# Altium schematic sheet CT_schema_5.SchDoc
size 573 x 363 mm
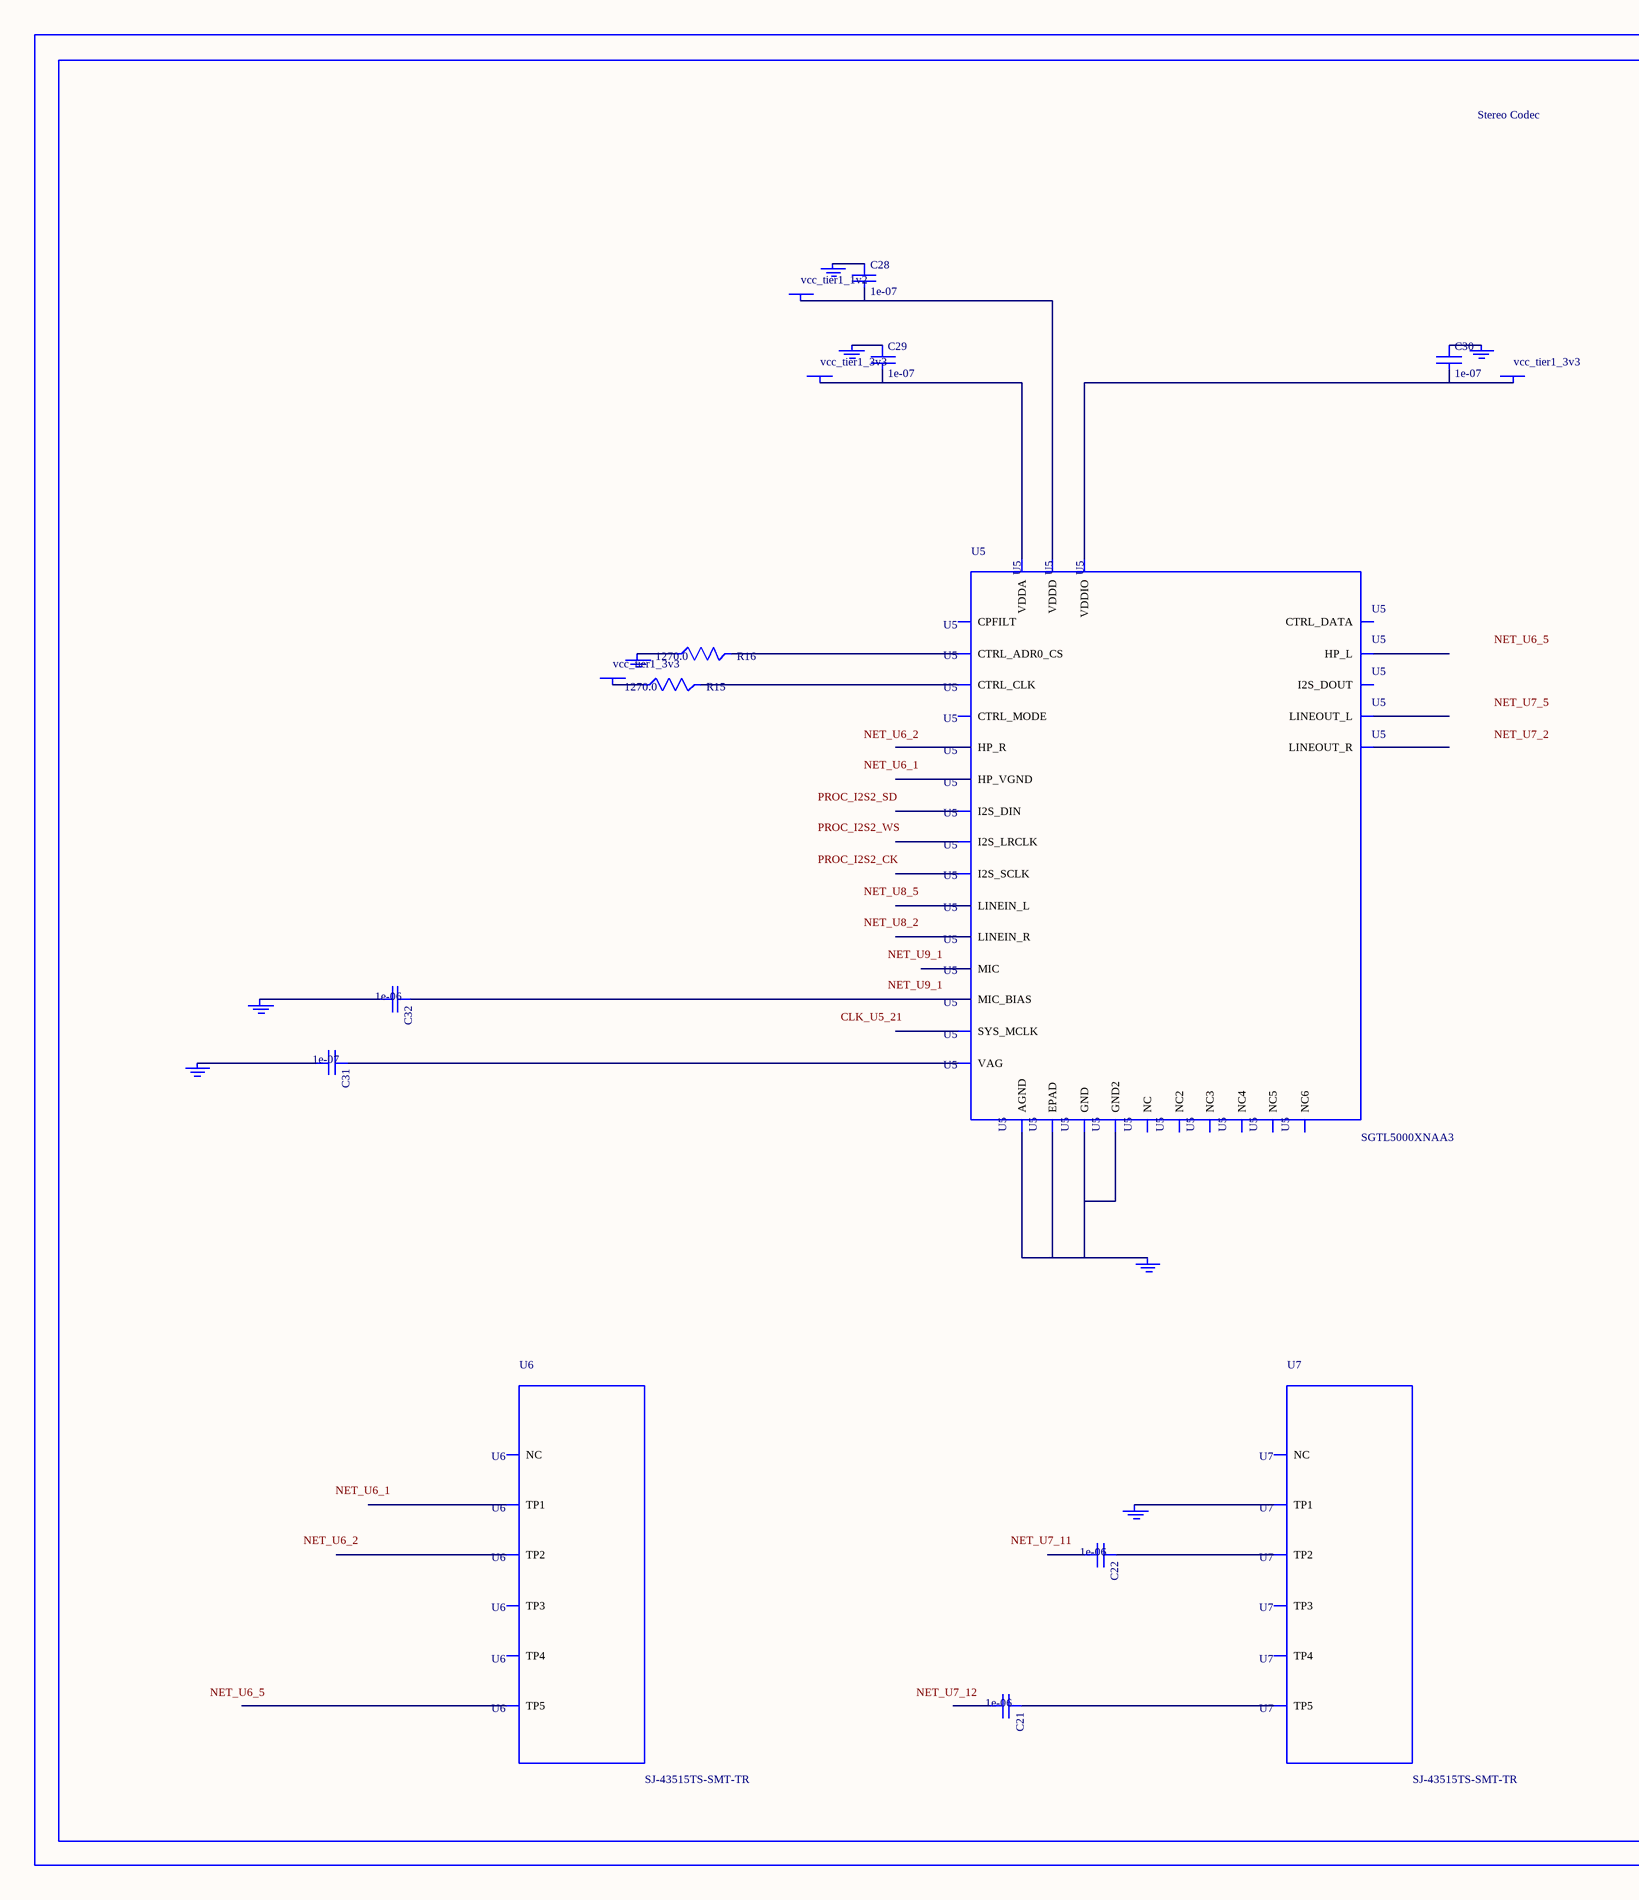
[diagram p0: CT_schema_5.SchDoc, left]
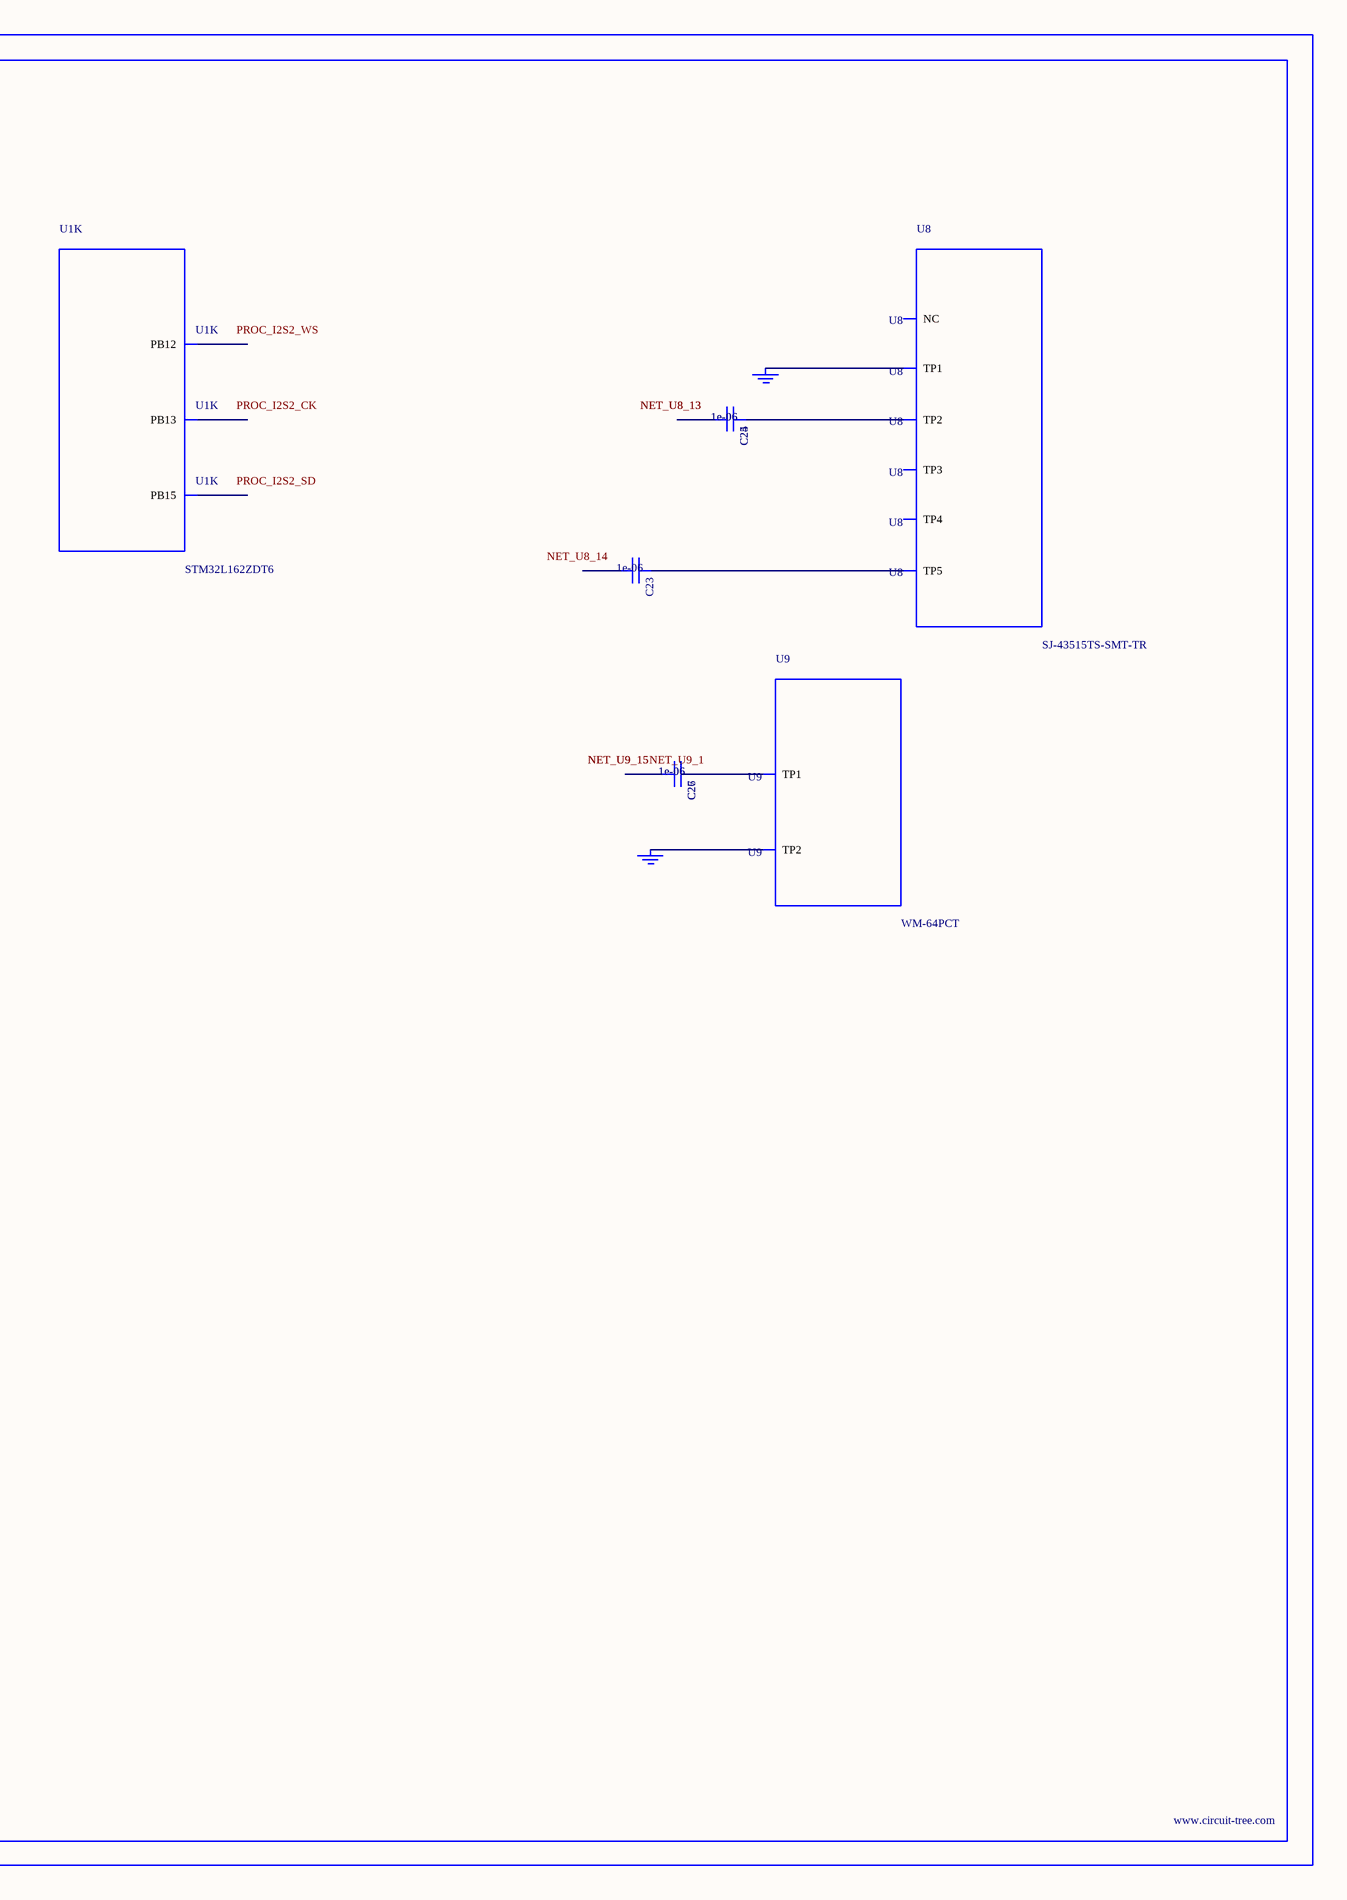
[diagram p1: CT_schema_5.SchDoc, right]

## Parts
BORDER4  (no value)
C21  1e-06  [C0603]
C22  1e-06  [C0603]
C23  1e-06  [C0603]
C24  1e-06  [C0603]
C25  1e-06  [C0603]
C26  1e-06  [C0603]
C27  1e-06  [C0603]
C28  1e-07  [C0402]
C29  1e-07  [C0402]
C30  1e-07  [C0402]
C31  1e-07  [C0402]
C32  1e-06  [C0603]
GND_INSTANCE_4_0  (no value)
GND_INSTANCE_4_1  (no value)
GND_INSTANCE_4_2  (no value)
GND_INSTANCE_4_3  (no value)
GND_INSTANCE_4_4  (no value)
GND_INSTANCE_4_5  (no value)
GND_INSTANCE_4_6  (no value)
GND_INSTANCE_4_7  (no value)
GND_INSTANCE_4_8  (no value)
GND_INSTANCE_4_9  (no value)
GND_INSTANCE_4_10  (no value)
POWER_INSTANCE_4_0  vcc_tier1_3v3
POWER_INSTANCE_4_1  vcc_tier1_3v3
POWER_INSTANCE_4_2  vcc_tier1_3v3
POWER_INSTANCE_4_3  vcc_tier1_1v2
R15  1270.0  [R0603]
R16  1270.0  [R0603]
U1  STM32L162ZDT6  [LQFP144]  (part K of 11)
U5  SGTL5000XNAA3  [QFN-32]
U6  SJ-43515TS-SMT-TR  [SJ-43515TS-SMT-TR]
U7  SJ-43515TS-SMT-TR  [SJ-43515TS-SMT-TR]
U8  SJ-43515TS-SMT-TR  [SJ-43515TS-SMT-TR]
U9  WM-64PCT  [WM-64PC]

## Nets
NetC21_1: C21.1 U7.5(TP5)
NetC22_1: C22.1 U7.2(TP2)
NetC23_1: C23.1 U8.5(TP5)
NetC24_1: C24.1 C25.1 U8.2(TP2)
NetC24_2: C24.2 C25.2
NetC26_1: C26.1 C27.1 U9.1(TP1)
NetC26_2: C26.2 C27.2
NetC28_1: C28.1 GND_INSTANCE_4_5.0(GND)
NetC28_2: C28.2 POWER_INSTANCE_4_3.0(PWR) U5.30(VDDD)
NetC29_1: C29.1 GND_INSTANCE_4_1.0(GND)
NetC29_2: C29.2 POWER_INSTANCE_4_0.0(PWR) U5.5(VDDA)
NetC30_1: C30.1 GND_INSTANCE_4_4.0(GND)
NetC30_2: C30.2 POWER_INSTANCE_4_1.0(PWR) U5.20(VDDIO)
NetC31_1: C31.1 U5.10(VAG)
NetC31_2: C31.2 GND_INSTANCE_4_2.0(GND)
NetC32_1: C32.1 U5.16(MIC_BIAS)
NetC32_2: C32.2 GND_INSTANCE_4_3.0(GND)
NetGND_INSTANCE_4_0_0: GND_INSTANCE_4_0.0(GND) U5.1(GND) U5.3(GND2) U5.7(AGND) U5.EXP(EPAD)
NetGND_INSTANCE_4_6_0: GND_INSTANCE_4_6.0(GND) R16.1
NetGND_INSTANCE_4_7_0: GND_INSTANCE_4_7.0(GND) U7.1(TP1)
NetGND_INSTANCE_4_8_0: GND_INSTANCE_4_8.0(GND) GND_INSTANCE_4_9.0(GND) U8.1(TP1)
NetGND_INSTANCE_4_10_0: GND_INSTANCE_4_10.0(GND) U9.2(TP2)
NetPOWER_INSTANCE_4_2_0: POWER_INSTANCE_4_2.0(PWR) R15.1
NetR15_2: R15.2 U5.29(CTRL_CLK)
NetR16_2: R16.2 U5.31(CTRL_ADR0_CS)

Not connected (* = marked no-connect by the designer): C21 2; C22 2; C23 2; U1 73(PB12) 74(PB13) 76(PB15); U5 2(HP_R) 4(HP_VGND) 6(HP_L) 8(NC) 9(NC2) 11(LINEOUT_R) 12(LINEOUT_L) 13(LINEIN_R) 14(LINEIN_L) 15(MIC) 17(NC3) 18(CPFILT) 19(NC4) 21(SYS_MCLK) 22(NC5) 23(I2S_LRCLK) 24(I2S_SCLK) 25(I2S_DOUT) 26(I2S_DIN) 27(CTRL_DATA) 28(NC6) 32(CTRL_MODE); U6 1(TP1) 2(TP2) 3(TP3) 4(TP4) 5(TP5) 6(NC); U7 3(TP3) 4(TP4) 6(NC); U8 3(TP3) 4(TP4) 6(NC)

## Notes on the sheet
- Labels drawn without touching a wire or pin: CLK_U5_21, NET_U6_1, NET_U6_2, NET_U6_5, NET_U7_2, NET_U7_5, NET_U7_11, NET_U7_12, NET_U8_2, NET_U8_5, NET_U8_14, NET_U9_1, PROC_I2S2_CK, PROC_I2S2_SD, PROC_I2S2_WS

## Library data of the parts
BORDER4 = BORDER_PAGE4
C21-C27 C32 = C0603C105K3RACTU
C28-C31 = C0402C104K3RACTU
GND_INSTANCE_4_0-GND_INSTANCE_4_10 = GND
POWER_INSTANCE_4_0-POWER_INSTANCE_4_3 = PWR
R15 R16 = RC0603FR-071K27L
